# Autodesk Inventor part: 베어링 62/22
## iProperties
Created: 2009-02
Part Number: 베어링 62/22
Material: 강, 연강
Description: 깊은 그루브 볼 베어링
Document SubType Name: Modeling
Standard: KS B 2023
Designer: KYOUNG IL JANG
Standards Organization: KS
Language: ko-KR
Size Designation: 62/22 - 22 x 50 x 14
Categories: <MemberInstance><Categories><Category DisplayName="샤프트 부품" InternalName="7f7aeb1f-a693-4053-b835-cee3144e0d98" Mnemonic="SHFT"><Category DisplayName="베어링" Inter
Density: 1 g/cm^3
IsCustomPart: 0
Author: KYOUNG IL JANG
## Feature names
1. IDS_ARRAYBALL[SIMPL:T] [Circular Pattern]
